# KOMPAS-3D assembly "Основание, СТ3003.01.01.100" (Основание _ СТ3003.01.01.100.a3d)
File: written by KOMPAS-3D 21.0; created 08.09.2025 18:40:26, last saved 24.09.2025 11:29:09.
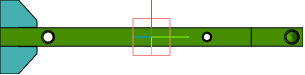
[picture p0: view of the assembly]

Document properties: Полное имя файла: C:\Users\1\Yandex.Disk\Документы\Новая папка\Стапель №2\Стапель _ СТ3003.00.00.000\Опора _ СТ3003.01.00.000\3D\Кронштейн _ СТ3003.01.01.000\Основание _ СТ3003.01.01.100\Основание _ СТ3003.01.01.100.a3d

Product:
- Part/product: Основание  | designation СТ3003.01.01.100
    Масса: 4.086618
    Форматы листов документа: A3
  - Component [detail]: Пластина  | designation СТ3003.01.01.101  | pos. 1  | Материал: Лист$dБ-ПН-НО-25 ГОСТ 19903-2015;Ст3сп ГОСТ 14637-89$ (density 7850 kg/m3); Масса: 3.643787; Форматы листов документа: A2; source file: ..\..\..\2D\Кронштейн _ СТ3003.01.01.000\Основание _ СТ3003.01.01.100\Пластина _ СТ3003.01.01.101.cdw, Пластина _ СТ3003.01.01.101.m3d
  - Component [detail]: Пластина  | designation СТ3003.01.01.102  | pos. 2  | Материал: Лист$dБ-ПН-НО-16 ГОСТ 19903-2015;Ст3сп ГОСТ 14637-89$ (density 7850 kg/m3); Масса: 0.442831; Форматы листов документа: A4; source file: ..\..\..\2D\Кронштейн _ СТ3003.01.01.000\Основание _ СТ3003.01.01.100\Пластина _ СТ3003.01.01.102.cdw, Пластина _ СТ3003.01.01.102.m3d

Referenced files in C:\Users\1\Yandex.Disk\Документы\Новая папка\Стапель №2\Стапель _ СТ3003.00.00.000\Опора _ СТ3003.01.00.000\3D\Кронштейн _ СТ3003.01.01.000\Основание _ СТ3003.01.01.100\: Пластина _ СТ3003.01.01.101.m3d, Пластина _ СТ3003.01.01.102.m3d
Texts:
  СТ3003.01.01.100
